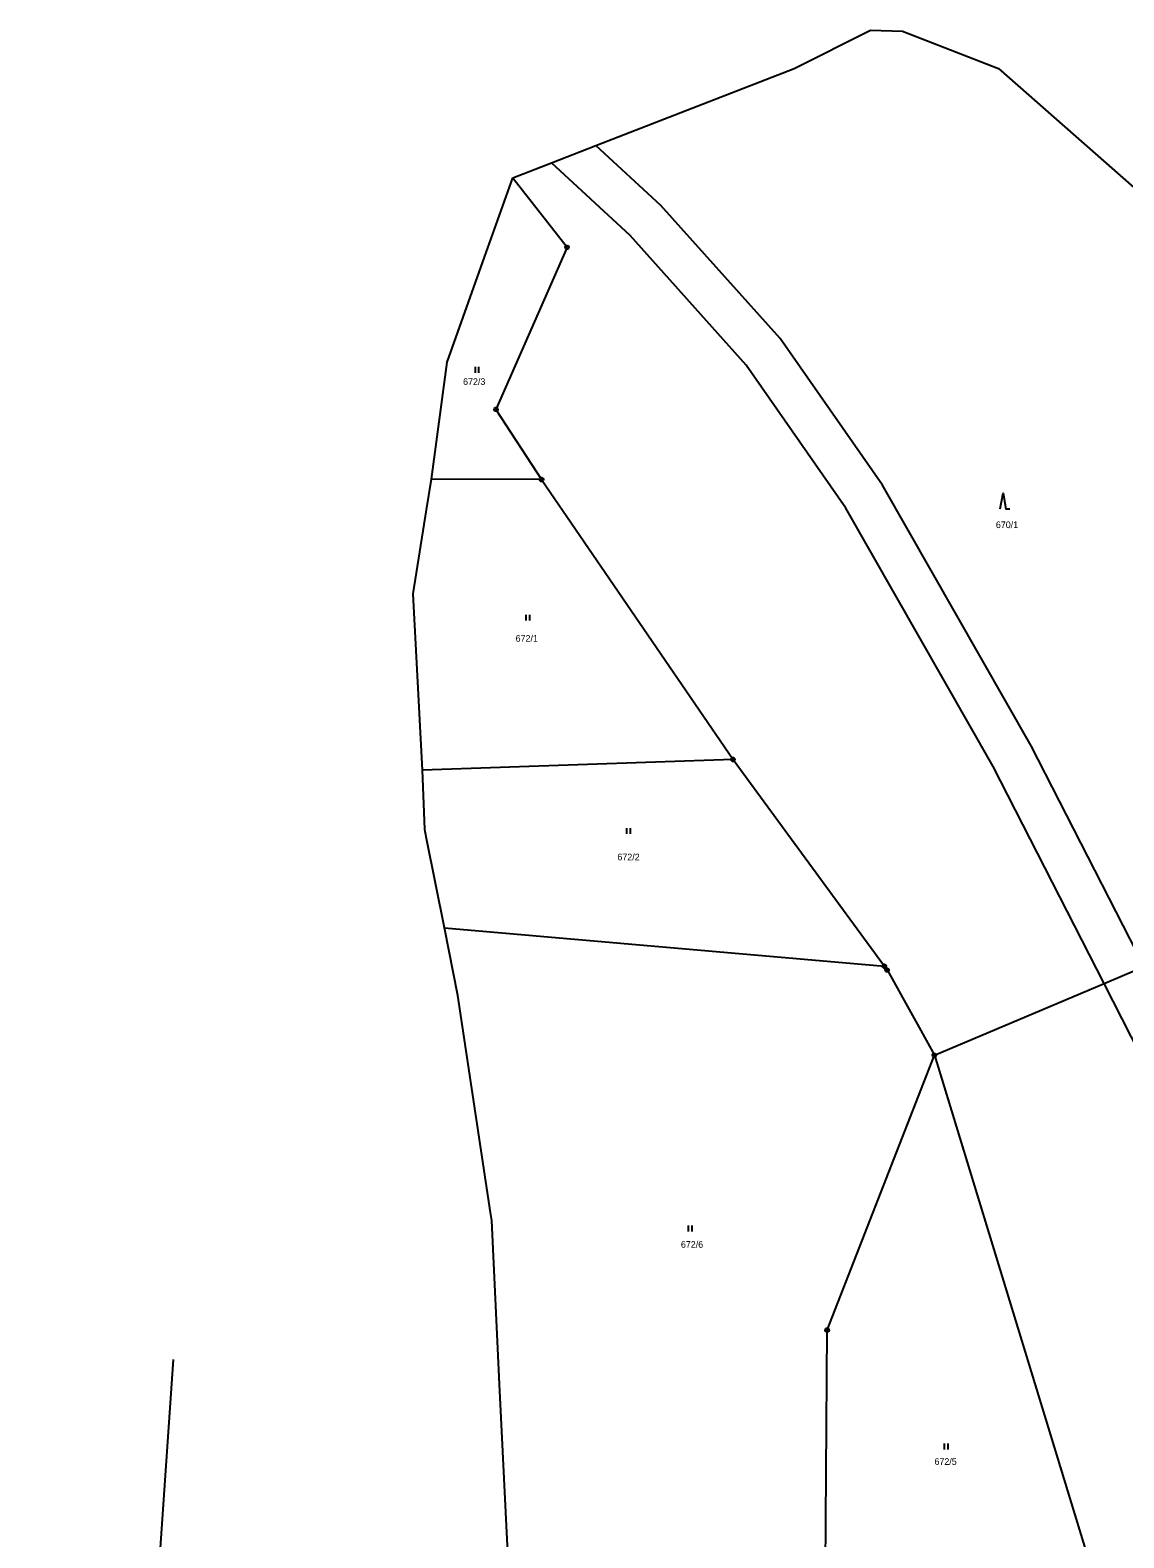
# Model space of a CAD drawing. Extents: x -694465 to -690527, y -983694 to -978978.
# Drawn here: x -693355.2 to -693075.3, y -983133.7 to -982748.2 of the extents above; entities that cross this region are included whole.
import ezdxf

# ---------------------------------------------------------------- set-up
doc = ezdxf.new("R2010")
doc.units = 0
for name, color, linetype in [('Vrstva 1', 7, 'Continuous'), ('Vrstva 18', 7, 'Continuous'), ('Vrstva 24', 7, 'Continuous'), ('Vrstva 25', 7, 'Continuous')]:
    doc.layers.add(name, color=color, linetype=linetype)

msp = doc.modelspace()

# ---------------------------------------------------------------- linework, layer by layer
at = {"layer": 'Vrstva 1'}
msp.add_line((-693355.154, -983621.195), (-693318.485, -983088.152), dxfattribs=at)
for points in [[(-693210.393, -982777.707), (-693159.71, -982758.02), (-693140.16, -982748.2), (-693131.99, -982748.44), (-693107.44, -982757.99), (-693063.56, -982796.53), (-693040.5, -982808.23), (-693023.22, -982813), (-693014.55, -982821.79), (-692999.44, -982808.91), (-692995.64, -982805.67)], [(-693221.749, -982782.118), (-693210.393, -982777.707)], [(-693070.091, -982987.841), (-693099.057, -982931.222), (-693137.122, -982864.574), (-693163.283, -982827.058), (-693193.81, -982793.026), (-693210.393, -982777.707)], [(-693231.69, -982785.98), (-693221.749, -982782.118)], [(-693080.387, -982991.977), (-693108.735, -982936.456), (-693146.428, -982870.46), (-693171.921, -982833.902), (-693201.658, -982800.75), (-693221.749, -982782.118)], [(-693252.48, -982863.02), (-693248.48, -982833.13), (-693238.9, -982806.24), (-693231.69, -982785.98)], [(-693231.69, -982785.98), (-693217.79, -982803.72)], [(-693217.79, -982803.72), (-693235.97, -982845.18)], [(-693235.97, -982845.18), (-693224.3, -982863.11)], [(-693254.75, -982937.41), (-693257.16, -982892.38), (-693253.73, -982870.89), (-693252.48, -982863.02)], [(-693224.3, -982863.11), (-693252.48, -982863.02)], [(-693224.3, -982863.11), (-693175.31, -982934.7)], [(-693175.31, -982934.7), (-693254.75, -982937.41)], [(-693249.17, -982977.79), (-693253.63, -982955.3), (-693254.06, -982953.14), (-693254.19, -982952.51), (-693254.75, -982937.41)], [(-693175.31, -982934.7), (-693136.61, -982987.55)], [(-693233.06, -983144.46), (-693233.02, -983135.82), (-693235.03, -983094.41), (-693237.05, -983052.62), (-693237.37, -983050.52), (-693245.74, -982995.09), (-693249.17, -982977.79)], [(-693249.17, -982977.79), (-693136.61, -982987.55)], [(-693136.61, -982987.55), (-693135.91, -982988.52)], [(-693135.91, -982988.52), (-693123.81, -983010.35)], [(-693123.81, -983010.35), (-693080.387, -982991.977)], [(-693080.387, -982991.977), (-693071.72, -982988.31)], [(-693052.335, -983050.557), (-693071.136, -983010.025), (-693080.387, -982991.977)], [(-693151.23, -983080.59), (-693123.81, -983010.35)], [(-693123.81, -983010.35), (-693078.94, -983157.17)], [(-693151.76, -983153.58), (-693151.23, -983080.59)]]:
    msp.add_lwpolyline(points, dxfattribs=at)
at = {"layer": 'Vrstva 24'}
for points in [[(-693217.636, -982803.244), (-693217.386, -982803.426), (-693217.29, -982803.72), (-693217.386, -982804.014), (-693217.636, -982804.196), (-693217.944, -982804.196), (-693218.194, -982804.014), (-693218.29, -982803.72), (-693218.194, -982803.426), (-693217.944, -982803.244)], [(-693235.816, -982844.704), (-693235.566, -982844.886), (-693235.47, -982845.18), (-693235.566, -982845.474), (-693235.816, -982845.656), (-693236.124, -982845.656), (-693236.374, -982845.474), (-693236.47, -982845.18), (-693236.374, -982844.886), (-693236.124, -982844.704)], [(-693224.146, -982862.634), (-693223.896, -982862.816), (-693223.8, -982863.11), (-693223.896, -982863.404), (-693224.146, -982863.586), (-693224.454, -982863.586), (-693224.704, -982863.404), (-693224.8, -982863.11), (-693224.704, -982862.816), (-693224.454, -982862.634)], [(-693175.156, -982934.224), (-693174.906, -982934.406), (-693174.81, -982934.7), (-693174.906, -982934.994), (-693175.156, -982935.176), (-693175.464, -982935.176), (-693175.714, -982934.994), (-693175.81, -982934.7), (-693175.714, -982934.406), (-693175.464, -982934.224)], [(-693136.456, -982987.074), (-693136.206, -982987.256), (-693136.11, -982987.55), (-693136.206, -982987.844), (-693136.456, -982988.026), (-693136.764, -982988.026), (-693137.014, -982987.844), (-693137.11, -982987.55), (-693137.014, -982987.256), (-693136.764, -982987.074)], [(-693135.756, -982988.044), (-693135.506, -982988.226), (-693135.41, -982988.52), (-693135.506, -982988.814), (-693135.756, -982988.996), (-693136.064, -982988.996), (-693136.314, -982988.814), (-693136.41, -982988.52), (-693136.314, -982988.226), (-693136.064, -982988.044)], [(-693123.656, -983009.874), (-693123.406, -983010.056), (-693123.31, -983010.35), (-693123.406, -983010.644), (-693123.656, -983010.826), (-693123.964, -983010.826), (-693124.214, -983010.644), (-693124.31, -983010.35), (-693124.214, -983010.056), (-693123.964, -983009.874)], [(-693151.076, -983080.114), (-693150.826, -983080.296), (-693150.73, -983080.59), (-693150.826, -983080.884), (-693151.076, -983081.066), (-693151.384, -983081.066), (-693151.634, -983080.884), (-693151.73, -983080.59), (-693151.634, -983080.296), (-693151.384, -983080.114)]]:
    msp.add_lwpolyline(points, close=True, dxfattribs=at)
for points in [[(-693217.909, -982803.72), (-693217.67, -982803.72)], [(-693236.089, -982845.18), (-693235.85, -982845.18)], [(-693224.419, -982863.11), (-693224.18, -982863.11)], [(-693175.429, -982934.7), (-693175.19, -982934.7)], [(-693136.729, -982987.55), (-693136.49, -982987.55)], [(-693136.029, -982988.52), (-693135.79, -982988.52)], [(-693123.929, -983010.35), (-693123.69, -983010.35)], [(-693151.349, -983080.59), (-693151.11, -983080.59)]]:
    msp.add_lwpolyline(points, dxfattribs=at)
at = {"layer": 'Vrstva 25'}
for points in [[(-693241.33, -982834.29), (-693241.33, -982835.79)], [(-693240.33, -982835.79), (-693240.33, -982834.29)], [(-693106.99, -982870.58), (-693106.24, -982866.58), (-693105.49, -982870.58), (-693104.49, -982870.58)], [(-693228.32, -982897.69), (-693228.32, -982899.19)], [(-693227.32, -982899.19), (-693227.32, -982897.69)], [(-693202.57, -982952.22), (-693202.57, -982953.72)], [(-693201.57, -982953.72), (-693201.57, -982952.22)], [(-693186.78, -983053.86), (-693186.78, -983055.36)], [(-693185.78, -983055.36), (-693185.78, -983053.86)], [(-693121.32, -983109.62), (-693121.32, -983111.12)], [(-693120.32, -983111.12), (-693120.32, -983109.62)]]:
    msp.add_lwpolyline(points, dxfattribs=at)

# ---------------------------------------------------------------- texts
at = {"layer": 'Vrstva 18'}
for s, p in [('672/3', (-693244.384, -982838.92)), ('670/1', (-693108.073, -982875.53)), ('672/1', (-693230.939, -982904.59)), ('672/2', (-693204.9, -982960.49)), ('672/6', (-693188.653, -983059.56)), ('672/5', (-693123.783, -983115.07))]:
    msp.add_text(s, height=1.7, dxfattribs=at).set_placement(p)

doc.saveas('drawing.dxf')
